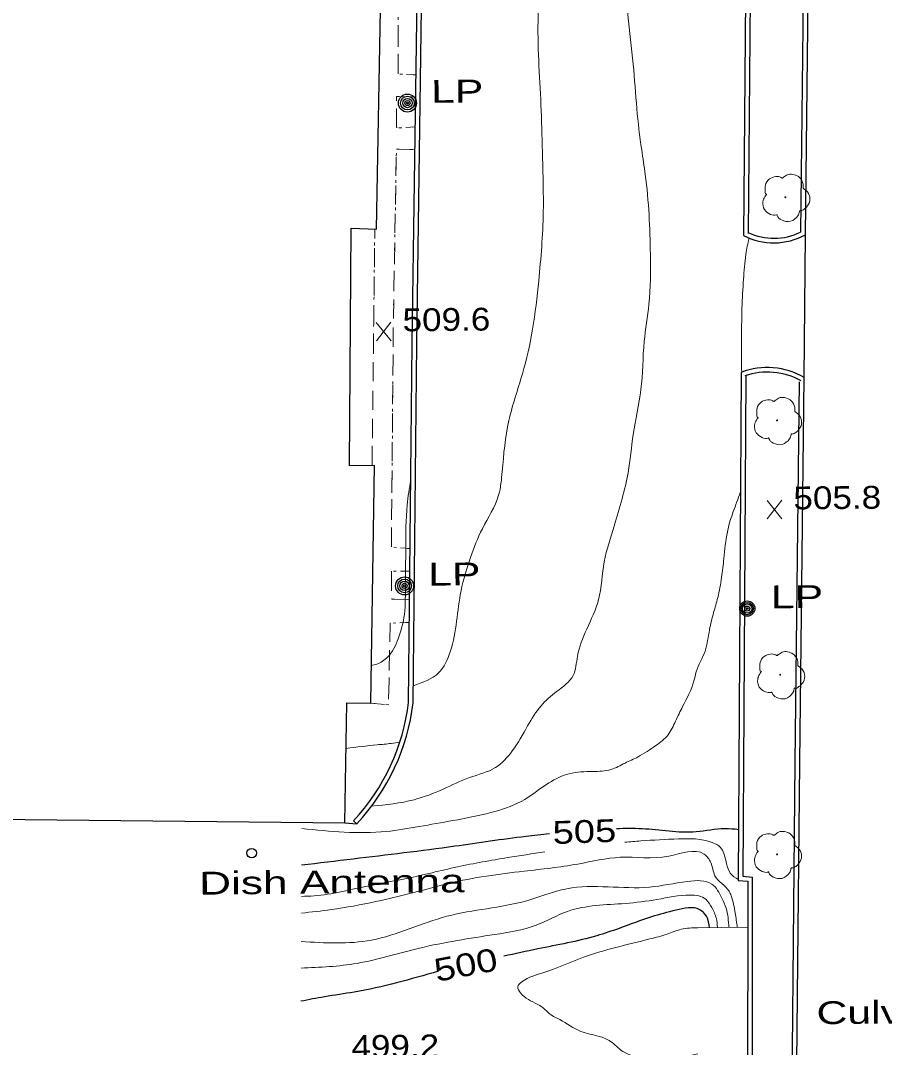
# Model space of a CAD drawing. Extents: x 2362213 to 2366494, y 6968794 to 6978110.
# Drawn here: x 2364072.1 to 2364253.9, y 6975258.2 to 6975474.3 of the extents above; entities that cross this region are included whole.
import ezdxf
from ezdxf.enums import TextEntityAlignment as Align

# ---------------------------------------------------------------- set-up
doc = ezdxf.new("R2010")
doc.units = 0
doc.header["$LTSCALE"] = 1.9
doc.linetypes.add('DOTTED', pattern=[1.5, 0.3, -1.2])
for name, color, linetype, lineweight in [('11', 7, 'Continuous', 25), ('12', 7, 'Continuous', 25), ('13', 7, 'Continuous', 13), ('2', 7, 'Continuous', 25), ('20', 7, 'Continuous', 25), ('29', 7, 'Continuous', 13), ('31', 7, 'Continuous', 25), ('35', 7, 'Continuous', 13), ('9', 7, 'Continuous', 13)]:
    doc.layers.add(name, color=color, linetype=linetype, lineweight=lineweight)

msp = doc.modelspace()

# ---------------------------------------------------------------- linework, layer by layer
at = {"layer": '11'}
msp.add_lwpolyline([(2363982.848, 6975662.41), (2363978.601, 6975307.142), (2364140.395, 6975305.463), (2364140.804, 6975330.719), (2364145.825, 6975330.666), (2364146.589, 6975380.696), (2364141.338, 6975380.606), (2364141.712, 6975430.622), (2364147.015, 6975430.402), (2364147.958, 6975480.533), (2364142.276, 6975480.599), (2364142.448, 6975505.642), (2364148.032, 6975505.265), (2364148.793, 6975555.576), (2364143.044, 6975555.461), (2364143.564, 6975580.656), (2364148.896, 6975580.507), (2364149.503, 6975630.145), (2364144.578, 6975629.678), (2364144.59, 6975659.93)], dxfattribs=at)
at = {"layer": '12'}
msp.add_circle((2364120.754, 6975299.116), 1, dxfattribs=at)
at = {"layer": '13'}
for p, q in [((2364151.575, 6975469.297), (2364151.577, 6975473.298)), ((2364151.572, 6975463.297), (2364151.574, 6975467.297)), ((2364155.336, 6975462.873), (2364153.335, 6975462.975)), ((2364151.272, 6975451.794), (2364151.244, 6975455.794)), ((2364155.171, 6975451.901), (2364153.172, 6975451.792)), ((2364151.129, 6975441.622), (2364151.201, 6975445.623)), ((2364151.615, 6975447.227), (2364155.106, 6975447.15)), ((2364151.016, 6975435.621), (2364151.088, 6975439.621)), ((2364150.913, 6975429.619), (2364150.985, 6975433.62)), ((2364146.665, 6975430.419), (2364146.644, 6975428.419)), ((2364146.623, 6975426.418), (2364146.581, 6975422.418)), ((2364150.8, 6975423.618), (2364150.872, 6975427.619)), ((2364150.697, 6975417.616), (2364150.769, 6975421.618)), ((2364146.56, 6975420.417), (2364146.518, 6975416.417)), ((2364146.498, 6975414.417), (2364146.446, 6975410.416)), ((2364150.532, 6975405.615), (2364150.563, 6975409.615)), ((2364146.425, 6975408.416), (2364146.373, 6975404.415)), ((2364146.352, 6975402.415), (2364146.31, 6975398.414)), ((2364150.479, 6975399.614), (2364150.511, 6975403.614)), ((2364146.289, 6975396.413), (2364146.237, 6975392.413)), ((2364150.426, 6975393.612), (2364150.458, 6975397.614)), ((2364150.373, 6975387.612), (2364150.405, 6975391.613)), ((2364146.216, 6975390.413), (2364146.164, 6975386.412)), ((2364150.32, 6975381.611), (2364150.352, 6975385.612)), ((2364146.143, 6975384.412), (2364146.099, 6975380.691)), ((2364150.267, 6975375.611), (2364150.299, 6975379.611)), ((2364150.214, 6975369.61), (2364150.246, 6975373.609)), ((2364150.161, 6975363.609), (2364150.193, 6975367.61)), ((2364154.096, 6975363.187), (2364152.104, 6975363.378)), ((2364150.182, 6975358.279), (2364150.21, 6975354.279)), ((2364154.051, 6975358.436), (2364152.051, 6975358.427)), ((2364150.477, 6975352.532), (2364153.987, 6975352.515)), ((2364153.943, 6975347.663), (2364151.944, 6975347.584)), ((2364149.772, 6975341.544), (2364149.7, 6975337.544)), ((2364149.659, 6975335.543), (2364149.577, 6975331.542)), ((2364148.747, 6975330.424), (2364145.825, 6975330.666))]:
    msp.add_line(p, q, dxfattribs=at)
at = {"layer": '13', "linetype": 'DOTTED'}
msp.add_line((2364146.665, 6975430.419), (2364146.099, 6975380.691), dxfattribs=at)
for points in [[(2364155.336, 6975462.873), (2364151.575, 6975463.057), (2364151.585, 6975507.139), (2364152.008, 6975533.024), (2364156.327, 6975533.186)], [(2364155.171, 6975451.901), (2364151.273, 6975451.694), (2364151.23, 6975458.304), (2364155.261, 6975458.232)], [(2364154.096, 6975363.187), (2364150.162, 6975363.559), (2364150.584, 6975411.625), (2364151.225, 6975447.233), (2364155.106, 6975447.15)], [(2364154.051, 6975358.436), (2364150.181, 6975358.409), (2364150.227, 6975352.529), (2364153.987, 6975352.515)], [(2364153.943, 6975347.663), (2364149.895, 6975347.495), (2364149.558, 6975330.352), (2364145.825, 6975330.666)]]:
    msp.add_lwpolyline(points, dxfattribs=at)
at = {"layer": '13'}
for points in [[(2364151.235, 6975457.794), (2364151.23, 6975458.304), (2364154.721, 6975458.237)], [(2364150.584, 6975411.615), (2364150.584, 6975411.625), (2364150.656, 6975415.616)], [(2364149.945, 6975347.495), (2364149.895, 6975347.495), (2364149.813, 6975343.545)]]:
    msp.add_lwpolyline(points, dxfattribs=at)
at = {"layer": '2'}
for p, q in [((2364236.365, 6975429.763), (2364238.053, 6975584.416)), ((2364237.321, 6975429.232), (2364239.017, 6975585.005)), ((2364224.991, 6975516.299), (2364224.261, 6975429.088)), ((2364225.951, 6975516.288), (2364225.228, 6975429.467)), ((2364237.056, 6975399.208), (2364237.321, 6975429.232)), ((2364224.733, 6975399.531), (2364224.734, 6975399.441)), ((2364140.395, 6975305.463), (2364142.876, 6975305.276)), ((2364142.179, 6975305.93), (2364142.876, 6975305.276))]:
    msp.add_line(p, q, dxfattribs=at)
for points in [[(2364153.775, 6975330.732), (2364154.525, 6975406.323), (2364156.324, 6975532.437), (2364157.433, 6975658.622)], [(2364154.735, 6975330.721), (2364155.485, 6975406.312), (2364157.284, 6975532.426), (2364158.393, 6975658.611)], [(2364223.776, 6975400.272), (2364223.163, 6975293.391), (2364225.155, 6975293.19), (2364225.057, 6975200.565), (2364223.616, 6975076.795), (2364222.629, 6974979.891)], [(2364224.734, 6975399.441), (2364224.125, 6975294.26), (2364226.117, 6975294.059), (2364226.018, 6975200.554), (2364224.576, 6975076.784), (2364223.589, 6974979.88)], [(2364234.195, 6975219.863), (2364235.168, 6975318.197), (2364236.085, 6975398.299)], [(2364235.154, 6975219.852), (2364236.128, 6975318.186), (2364237.056, 6975399.208)]]:
    msp.add_lwpolyline(points, dxfattribs=at)
for centre, radius, start, end in [((2364230.656, 6975441.34), 13.821, 242.43972, 298.82981), ((2364230.656, 6975441.34), 12.861, 245.15289, 295.76956), ((2364229.303, 6975385.835), 15.458, 59.89352, 110.94888), ((2364229.303, 6975385.835), 14.498, 60.70049, 109.13026), ((2364109.971, 6975336.098), 44.126, 316.87353, 353.15067), ((2364109.971, 6975336.098), 45.086, 316.87353, 353.15067)]:
    msp.add_arc(centre, radius, start, end, dxfattribs=at)
at = {"layer": '20'}
for centre, radius in [((2364153.543, 6975456.936), 1.9), ((2364153.543, 6975456.936), 1.442), ((2364153.543, 6975456.936), 0.973), ((2364153.543, 6975456.936), 0.539), ((2364153.543, 6975456.936), 0.192), ((2364152.94, 6975355.345), 1.9), ((2364152.94, 6975355.345), 1.442), ((2364152.94, 6975355.345), 0.973), ((2364152.94, 6975355.345), 0.539), ((2364152.94, 6975355.345), 0.192), ((2364225.059, 6975350.572), 1.6), ((2364225.059, 6975350.572), 1.3), ((2364225.059, 6975350.572), 1), ((2364225.059, 6975350.572), 0.539), ((2364225.059, 6975350.572), 0.192)]:
    msp.add_circle(centre, radius, dxfattribs=at)
at = {"layer": '29'}
for centre in [(2364233.085, 6975437.112), (2364231.332, 6975390.153), (2364231.982, 6975336.657), (2364231.322, 6975298.849)]:
    msp.add_circle(centre, 0.1, dxfattribs=at)
for points in [[(2364229.12, 6975437.684), (2364229.14, 6975437.695), (2364229.059, 6975437.764), (2364228.823, 6975438.392), (2364228.861, 6975439.672), (2364229.748, 6975440.971), (2364231.054, 6975441.453), (2364232.177, 6975441.264), (2364232.408, 6975441.136), (2364232.478, 6975441.137), (2364232.528, 6975441.177), (2364232.875, 6975441.47), (2364233.74, 6975441.919), (2364234.95, 6975441.85), (2364236.066, 6975441.261), (2364236.8, 6975439.838), (2364236.808, 6975438.978)], [(2364236.798, 6975438.998), (2364237.938, 6975437.938), (2364238.223, 6975436.351), (2364237.515, 6975435.024), (2364236.861, 6975434.478), (2364236.193, 6975434.262), (2364236.043, 6975434.25), (2364236.024, 6975434.14), (2364235.702, 6975433.237), (2364234.163, 6975432.072), (2364232.272, 6975432.354), (2364231.372, 6975433.296), (2364231.3, 6975433.425), (2364231.181, 6975433.404), (2364229.969, 6975433.522), (2364228.7, 6975434.52), (2364228.354, 6975436.157), (2364228.724, 6975437.181), (2364229.05, 6975437.624), (2364229.12, 6975437.674)], [(2364227.367, 6975390.726), (2364227.387, 6975390.736), (2364227.306, 6975390.805), (2364227.07, 6975391.433), (2364227.108, 6975392.713), (2364227.995, 6975394.012), (2364229.301, 6975394.493), (2364230.423, 6975394.304), (2364230.654, 6975394.176), (2364230.724, 6975394.177), (2364230.774, 6975394.217), (2364231.121, 6975394.51), (2364231.988, 6975394.959), (2364233.198, 6975394.89), (2364234.313, 6975394.301), (2364235.047, 6975392.879), (2364235.055, 6975392.019)], [(2364235.045, 6975392.039), (2364236.185, 6975390.98), (2364236.47, 6975389.392), (2364235.762, 6975388.065), (2364235.108, 6975387.519), (2364234.44, 6975387.303), (2364234.29, 6975387.291), (2364234.271, 6975387.181), (2364233.949, 6975386.278), (2364232.411, 6975385.113), (2364230.518, 6975385.395), (2364229.619, 6975386.337), (2364229.547, 6975386.466), (2364229.428, 6975386.445), (2364228.216, 6975386.563), (2364226.947, 6975387.561), (2364226.601, 6975389.198), (2364226.972, 6975390.222), (2364227.297, 6975390.665), (2364227.367, 6975390.716)], [(2364228.016, 6975337.229), (2364228.036, 6975337.24), (2364227.955, 6975337.309), (2364227.719, 6975337.937), (2364227.757, 6975339.217), (2364228.645, 6975340.515), (2364229.95, 6975340.998), (2364231.072, 6975340.809), (2364231.303, 6975340.681), (2364231.373, 6975340.681), (2364231.423, 6975340.722), (2364231.771, 6975341.015), (2364232.637, 6975341.464), (2364233.848, 6975341.395), (2364234.962, 6975340.806), (2364235.696, 6975339.383), (2364235.704, 6975338.523)], [(2364235.694, 6975338.542), (2364236.834, 6975337.483), (2364237.119, 6975335.896), (2364236.412, 6975334.569), (2364235.757, 6975334.023), (2364235.089, 6975333.807), (2364234.939, 6975333.795), (2364234.92, 6975333.685), (2364234.599, 6975332.782), (2364233.061, 6975331.617), (2364231.167, 6975331.899), (2364230.268, 6975332.841), (2364230.197, 6975332.97), (2364230.077, 6975332.949), (2364228.866, 6975333.067), (2364227.596, 6975334.065), (2364227.251, 6975335.702), (2364227.621, 6975336.726), (2364227.947, 6975337.169), (2364228.016, 6975337.219)], [(2364227.356, 6975299.421), (2364227.376, 6975299.432), (2364227.295, 6975299.501), (2364227.059, 6975300.129), (2364227.097, 6975301.408), (2364227.985, 6975302.706), (2364229.29, 6975303.189), (2364230.412, 6975303), (2364230.643, 6975302.872), (2364230.713, 6975302.872), (2364230.763, 6975302.913), (2364231.11, 6975303.206), (2364231.977, 6975303.655), (2364233.188, 6975303.586), (2364234.302, 6975302.997), (2364235.036, 6975301.574), (2364235.044, 6975300.715)], [(2364235.034, 6975300.734), (2364236.174, 6975299.675), (2364236.459, 6975298.088), (2364235.752, 6975296.761), (2364235.097, 6975296.215), (2364234.429, 6975295.999), (2364234.28, 6975295.987), (2364234.261, 6975295.877), (2364233.94, 6975294.974), (2364232.401, 6975293.809), (2364230.507, 6975294.091), (2364229.608, 6975295.033), (2364229.537, 6975295.162), (2364229.417, 6975295.141), (2364228.206, 6975295.259), (2364226.936, 6975296.257), (2364226.591, 6975297.894), (2364226.961, 6975298.918), (2364227.287, 6975299.361), (2364227.356, 6975299.411)]]:
    msp.add_spline(points, degree=3, dxfattribs=at)
at = {"layer": '31', "lineweight": 13}
for p, q in [((2364150.089, 6975406.94), (2364146.972, 6975410.791)), ((2364147.009, 6975406.911), (2364150.052, 6975410.82)), ((2364232.34, 6975369.472), (2364229.223, 6975373.321)), ((2364229.26, 6975369.443), (2364232.303, 6975373.351))]:
    msp.add_line(p, q, dxfattribs=at)
at = {"layer": '31'}
for points in [[(2364183.459, 6975303.152), (2364178.464, 6975302.605), (2364163.493, 6975300.552), (2364142.116, 6975297.87), (2364131.269, 6975296.576)], [(2364223.222, 6975304.051), (2364220.36, 6975304.254), (2364214.286, 6975303.576), (2364202.909, 6975304.228), (2364197.559, 6975304.247)], [(2364217.098, 6975283.442), (2364216.485, 6975285.826), (2364215.082, 6975287.204), (2364210.064, 6975287.116), (2364204.896, 6975285.706), (2364198.098, 6975283.291), (2364193.383, 6975281.726), (2364180.949, 6975278.957), (2364173.853, 6975277.42)], [(2364276.12, 6975281.554), (2364275.394, 6975276.798), (2364274.325, 6975267.217), (2364273.318, 6975260.566), (2364272.393, 6975253.778), (2364271.255, 6975245.127), (2364270.354, 6975234.787), (2364269.478, 6975223.819), (2364268.782, 6975211.851), (2364267.945, 6975206.284), (2364266.017, 6975202.905), (2364263.472, 6975200.301), (2364261.504, 6975197.962), (2364260.014, 6975196.937), (2364253.758, 6975196.557), (2364248.316, 6975198.726), (2364242.457, 6975201.741), (2364234.994, 6975206.35)], [(2364160.063, 6975274.249), (2364142.363, 6975269.881), (2364136.063, 6975268.881), (2364131.111, 6975267.953)]]:
    msp.add_spline(points, degree=3, dxfattribs=at)
at = {"layer": '35'}
for points in [[(2364203.495, 6975658.57), (2364203.718, 6975655.132), (2364203.695, 6975651.262), (2364203.653, 6975644.052), (2364203.531, 6975636.95), (2364203.537, 6975633.15), (2364203.739, 6975627.731), (2364203.695, 6975619.752), (2364202.997, 6975613.184), (2364201.938, 6975602.594), (2364201.634, 6975595.721), (2364201.419, 6975585.687), (2364201.886, 6975572.331), (2364201.63, 6975563.578), (2364201.15, 6975554.054), (2364200.53, 6975544.667), (2364199.526, 6975531.398), (2364199.632, 6975520.257), (2364199.884, 6975504.319), (2364199.418, 6975487.034), (2364199.918, 6975475.498), (2364201.047, 6975465.088), (2364201.816, 6975455.785), (2364202.839, 6975447.085), (2364203.588, 6975441.891), (2364204.389, 6975433.429), (2364204.668, 6975425.111), (2364204.368, 6975414.588), (2364203.373, 6975406.748), (2364202.679, 6975396.631), (2364201.049, 6975387.195), (2364199.996, 6975379.154), (2364198.698, 6975373.671), (2364197.072, 6975367.936), (2364194.954, 6975360.436), (2364193.75, 6975352.424), (2364191.269, 6975346.23), (2364189.323, 6975340.551), (2364188.402, 6975336.482), (2364184.943, 6975333.109), (2364181.672, 6975330.137), (2364178.842, 6975325.88), (2364175.592, 6975320.609), (2364172.095, 6975317.136), (2364166.605, 6975315.014), (2364161.058, 6975312.581), (2364154.949, 6975310.362), (2364146.011, 6975309.007)], [(2364183.785, 6975658.523), (2364184.19, 6975656.896), (2364184.301, 6975654.747), (2364184.541, 6975650.4), (2364184.588, 6975644.521), (2364184.649, 6975638.08), (2364184.823, 6975634.402), (2364185.122, 6975629.294), (2364185.529, 6975622.239), (2364186.214, 6975612.304), (2364186.163, 6975607.113), (2364185.773, 6975592.479), (2364185.588, 6975583.516), (2364185.002, 6975568.53), (2364184.421, 6975557.044), (2364182.789, 6975539.368), (2364182.305, 6975528.313), (2364182.532, 6975513.834), (2364182.229, 6975500.561), (2364181.884, 6975488.497), (2364181.031, 6975474.088), (2364181.699, 6975455.384), (2364181.973, 6975445.466), (2364182.123, 6975433.947), (2364181.17, 6975419.527), (2364179.877, 6975409.354), (2364177.727, 6975399.933), (2364174.89, 6975390.116), (2364173.482, 6975379.412), (2364172.729, 6975374.434), (2364169.306, 6975367.382), (2364166.814, 6975361.298), (2364164.82, 6975354.328), (2364162.553, 6975341.496), (2364160.105, 6975337.053), (2364154.77, 6975334.342)], [(2364225.437, 6975428.539), (2364224.759, 6975425.102), (2364224.259, 6975419.857), (2364223.937, 6975413.794), (2364223.861, 6975409.123), (2364223.828, 6975406.333), (2364223.885, 6975400.313)], [(2364154.239, 6975377.549), (2364153.478, 6975372.42), (2364153.206, 6975363.118), (2364153.096, 6975355.767), (2364152.887, 6975349.353), (2364151.586, 6975344.222), (2364149.363, 6975340.371), (2364147.117, 6975338.899), (2364145.91, 6975338.578)], [(2364223.635, 6975375.129), (2364223.421, 6975374.497), (2364221.939, 6975370.503), (2364220.866, 6975366.673), (2364220.138, 6975361.105), (2364219.656, 6975357.121), (2364218.847, 6975352.873), (2364217.986, 6975349.773), (2364217.111, 6975346.126), (2364216.164, 6975341.637), (2364214.315, 6975337.249), (2364213.824, 6975335.344), (2364211.455, 6975329.96), (2364209.965, 6975326.916), (2364208.401, 6975324.002), (2364205.803, 6975321.747), (2364202.065, 6975319.371), (2364199.327, 6975318.055), (2364196.38, 6975316.727), (2364192.534, 6975316.301), (2364187.609, 6975315.834), (2364183.326, 6975313.903), (2364177.483, 6975309.987), (2364171.095, 6975307.665), (2364163.121, 6975305.969), (2364156.022, 6975304.721), (2364149.102, 6975303.665), (2364131.316, 6975304.286)], [(2364151.943, 6975322.494), (2364150.146, 6975322.197), (2364147.168, 6975321.909), (2364140.645, 6975321.137)], [(2364223.162, 6975293.541), (2364221.509, 6975294.865), (2364219.458, 6975300.286), (2364217.677, 6975301.368), (2364210.581, 6975302.111), (2364202.624, 6975301.675), (2364199.266, 6975301.403)], [(2364222.958, 6975283.488), (2364222.519, 6975286.505), (2364221.684, 6975290.137), (2364221.235, 6975291.093), (2364218.254, 6975294.354), (2364217.387, 6975297.146), (2364215.961, 6975298.903), (2364208.524, 6975298.482), (2364198.336, 6975298.235), (2364189.369, 6975296.819), (2364178.073, 6975295.322), (2364162.297, 6975292.772), (2364156.082, 6975291.152), (2364137.538, 6975287.246), (2364131.215, 6975286.495)], [(2364182.445, 6975299.374), (2364174.626, 6975298.179), (2364164.044, 6975296.218), (2364153.376, 6975293.797), (2364145.151, 6975292.198), (2364133.91, 6975290.141), (2364131.231, 6975290.016)], [(2364221.188, 6975283.471), (2364220.599, 6975287.516), (2364219.719, 6975289.608), (2364217.631, 6975292.588), (2364212.485, 6975293.169), (2364204.456, 6975291.963), (2364187.059, 6975291.617), (2364178.652, 6975289.107), (2364161.853, 6975285.826), (2364145.99, 6975280.815), (2364131.182, 6975280.534)], [(2364218.768, 6975283.458), (2364218.559, 6975285.386), (2364217.568, 6975287.648), (2364216.351, 6975289.406), (2364213.042, 6975290.295), (2364206.051, 6975289.368), (2364199.399, 6975288.535), (2364187.235, 6975286.859), (2364180.621, 6975283.955), (2364171.89, 6975281.991), (2364164.031, 6975280.726), (2364156.046, 6975279.13), (2364142.935, 6975275.926), (2364131.145, 6975274.924)], [(2364214.651, 6975256.857), (2364209.669, 6975256.05), (2364205.5, 6975255.89), (2364202.427, 6975256.161), (2364198.895, 6975257.377), (2364196.275, 6975259.513), (2364193.865, 6975260.57), (2364190.035, 6975261.613), (2364185.581, 6975264.092), (2364183.59, 6975265.233), (2364181.896, 6975266.707), (2364180.87, 6975267.327), (2364177.327, 6975269.734), (2364176.765, 6975270.998), (2364177.625, 6975272.047), (2364182.216, 6975273.99), (2364190.626, 6975277.231), (2364197.407, 6975279.264), (2364204.58, 6975281.063), (2364208.171, 6975282.067), (2364211.162, 6975283.085), (2364214.658, 6975283.419)]]:
    msp.add_spline(points, degree=3, dxfattribs=at)
at = {"layer": '9'}
msp.add_line((2364225.148, 6975283.509), (2364214.208, 6975283.414), dxfattribs=at)

# ---------------------------------------------------------------- texts
at = {"layer": '12', "width": 1.45}
msp.add_text('Dish Antenna', height=4.8, rotation=0.546, dxfattribs=at).set_placement((2364109.717, 6975290.371))
at = {"layer": '20', "width": 1.4}
for p in [(2364153.543, 6975456.936), (2364152.94, 6975355.345), (2364225.059, 6975350.571)]:
    msp.add_text('  LP', height=4.8, rotation=0.546, dxfattribs=at).set_placement(p)
at = {"layer": '31', "width": 1.15}
for s, p in [('509.6', (2364152.53, 6975408.904)), ('505.8', (2364234.781, 6975371.434)), ('499.2', (2364141.766, 6975255.993))]:
    msp.add_text(s, height=4.8, rotation=0.546, dxfattribs=at).set_placement(p)
at = {"layer": '31', "width": 1.25}
for s, rotation, p in [(' 505 ', 2.125, (2364190.869, 6975301.269)), (' 500 ', 10.794, (2364166.266, 6975273.267))]:
    msp.add_text(s, height=4.8, rotation=rotation, dxfattribs=at).set_placement(p, align=Align.CENTER)
at = {"layer": '9', "width": 1.4}
msp.add_text('Culvert', height=4.8, rotation=0.546, dxfattribs=at).set_placement((2364239.652, 6975263.116))

doc.saveas('drawing.dxf')
